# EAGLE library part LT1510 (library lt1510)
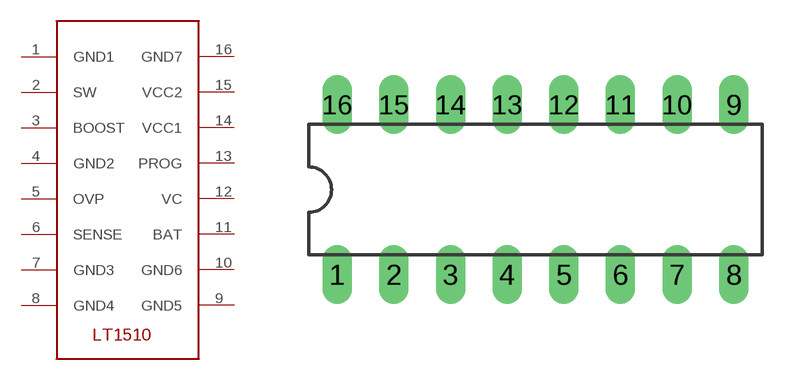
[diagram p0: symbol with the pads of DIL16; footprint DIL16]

Designator prefix -

## LT1510  [DIL16]
1  GND1
2  SW
3  BOOST
4  GND2
5  OVP
6  SENSE
7  GND3
8  GND4
9  GND5
10  GND6
11  BAT
12  VC
13  PROG
14  VCC1
15  VCC2
16  GND7

## Footprint DIL16 (pad centres in mm)
Dual In Line Package
drill 0.813 long: 1 -8.89,-3.81; 2 -6.35,-3.81; 3 -3.81,-3.81; 4 -1.27,-3.81; 5 1.27,-3.81; 6 3.81,-3.81; 7 6.35,-3.81; 8 8.89,-3.81; 9 8.89,3.81; 10 6.35,3.81; 11 3.81,3.81; 12 1.27,3.81; 13 -1.27,3.81; 14 -3.81,3.81; 15 -6.35,3.81; 16 -8.89,3.81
